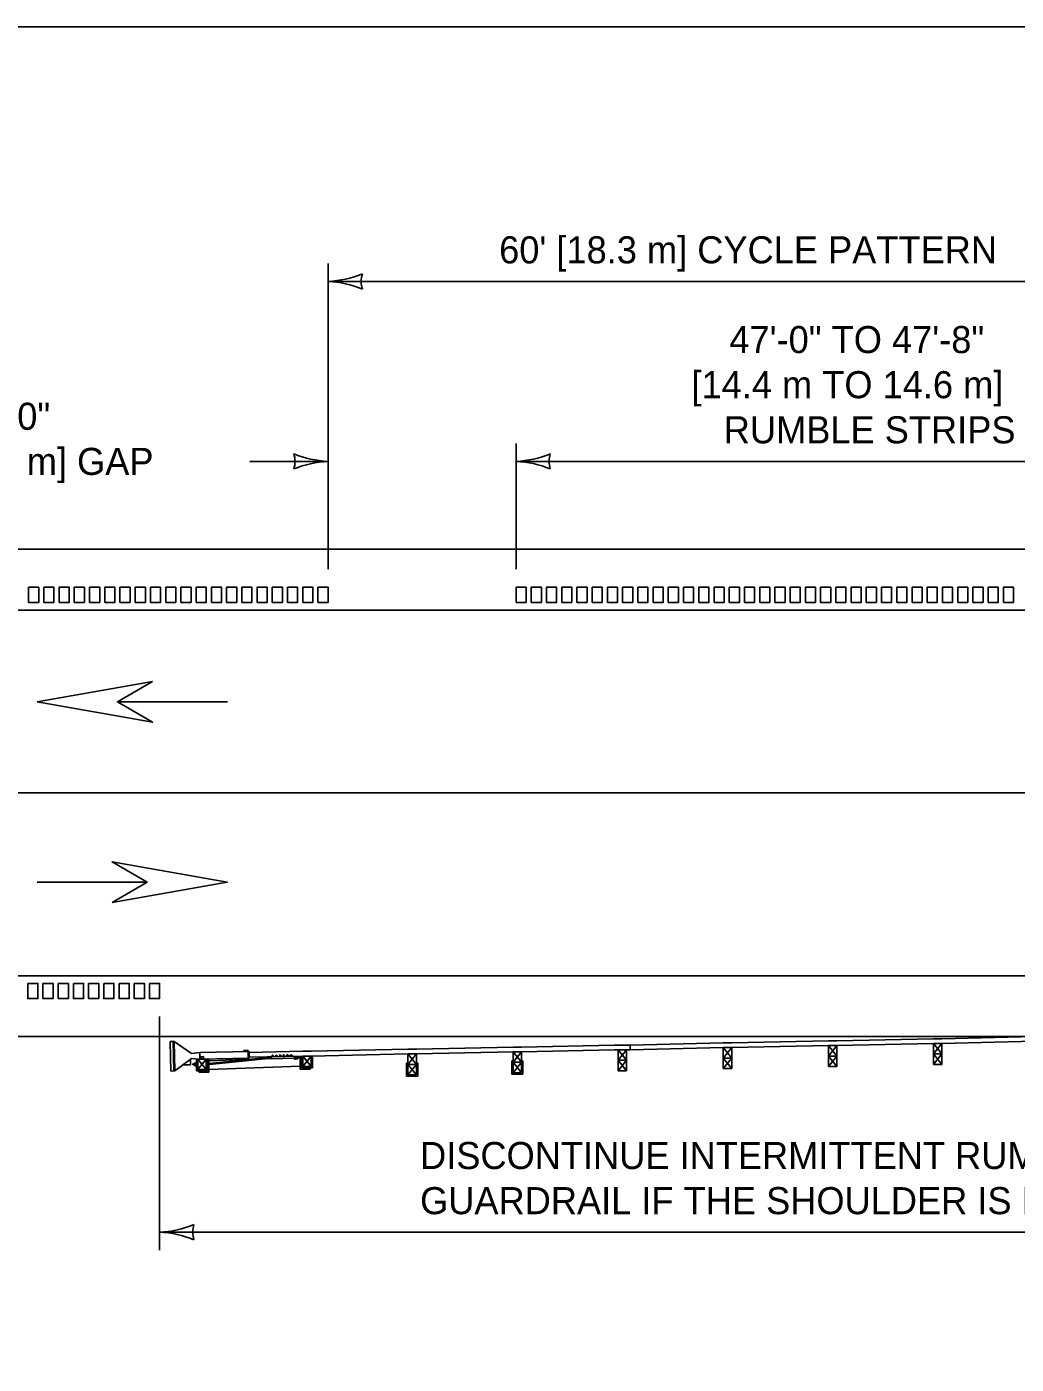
# Model space of a CAD drawing. Extents: x 49991.4 to 50021, y 49987.6 to 50011.4.
# Drawn here: x 50007.091 to 50009.283, y 49996.035 to 49998.999 of the extents above; entities that cross this region are included whole.
import ezdxf

# ---------------------------------------------------------------- set-up
doc = ezdxf.new("R2010")
doc.units = 0
for name, color, linetype in [('Level 1', 7, 'Continuous'), ('Level 2', 7, 'Continuous'), ('Level 3', 7, 'Continuous')]:
    doc.layers.add(name, color=color, linetype=linetype)

msp = doc.modelspace()

# ---------------------------------------------------------------- linework, layer by layer
at = {"layer": 'Level 1'}
for p, q in [((50011.3288, 49997.8413), (50005.1053, 49997.8413)), ((50011.3288, 49997.7063), (50005.1053, 49997.7063)), ((50007.5356, 49997.5032), (50007.2917, 49997.5032)), ((50007.5356, 49997.5029), (50007.2917, 49997.5029)), ((50011.3288, 49997.3013), (50005.1053, 49997.3013)), ((50007.1138, 49997.1035), (50007.3577, 49997.1035)), ((50007.1138, 49997.1033), (50007.3577, 49997.1033)), ((50011.3288, 49996.8963), (50005.1053, 49996.8963)), ((50007.3676, 49996.7613), (50005.1053, 49996.7613)), ((50009.4632, 49996.7613), (50007.3676, 49996.7613)), ((50009.0999, 49996.7567), (50008.8856, 49996.752)), ((50009.0999, 49996.7567), (50009.1185, 49996.7567)), ((50009.3237, 49996.7613), (50009.1185, 49996.7567)), ((50007.4084, 49996.7501), (50007.4177, 49996.7503)), ((50007.4097, 49996.6849), (50007.4084, 49996.7501)), ((50007.4168, 49996.6851), (50007.4155, 49996.7503)), ((50007.419, 49996.6851), (50007.4177, 49996.7503)), ((50007.4177, 49996.7503), (50007.4555, 49996.724)), ((50007.4555, 49996.724), (50007.4741, 49996.7263)), ((50007.5834, 49996.7285), (50007.4741, 49996.7263)), ((50007.4744, 49996.7114), (50007.4741, 49996.7263)), ((50007.5812, 49996.7307), (50007.5719, 49996.7305)), ((50007.5719, 49996.7283), (50007.5719, 49996.7305)), ((50007.5816, 49996.7114), (50007.5812, 49996.7307)), ((50007.7026, 49996.7287), (50007.5834, 49996.7263)), ((50007.5837, 49996.7136), (50007.5834, 49996.7285)), ((50007.7026, 49996.7287), (50007.7213, 49996.7287)), ((50007.9355, 49996.7334), (50007.7213, 49996.7287)), ((50007.7213, 49996.7183), (50007.9355, 49996.723)), ((50007.9355, 49996.7334), (50007.9541, 49996.7334)), ((50007.9355, 49996.723), (50007.9541, 49996.6997)), ((50007.9355, 49996.6997), (50007.9541, 49996.723)), ((50007.9355, 49996.723), (50007.9355, 49996.6764)), ((50007.9355, 49996.723), (50007.9541, 49996.723)), ((50008.1684, 49996.7381), (50007.9541, 49996.7334)), ((50007.9541, 49996.723), (50008.1684, 49996.7276)), ((50007.9541, 49996.6764), (50007.9541, 49996.723)), ((50008.1684, 49996.7381), (50008.187, 49996.7381)), ((50008.1684, 49996.7276), (50008.187, 49996.7043)), ((50008.1684, 49996.7043), (50008.187, 49996.7276)), ((50008.1684, 49996.7276), (50008.1684, 49996.681)), ((50008.1684, 49996.7276), (50008.187, 49996.7276)), ((50008.3922, 49996.7427), (50008.187, 49996.7381)), ((50008.187, 49996.7276), (50008.3922, 49996.7323)), ((50008.187, 49996.681), (50008.187, 49996.7276)), ((50008.3922, 49996.7427), (50008.4277, 49996.7427)), ((50008.3922, 49996.7323), (50008.4277, 49996.7323)), ((50008.4013, 49996.7323), (50008.4199, 49996.709)), ((50008.4013, 49996.709), (50008.4199, 49996.7323)), ((50008.4013, 49996.7323), (50008.4013, 49996.6857)), ((50008.4199, 49996.6857), (50008.4199, 49996.7323)), ((50008.6341, 49996.7474), (50008.4277, 49996.7427)), ((50008.4277, 49996.7323), (50008.4277, 49996.7427)), ((50008.4277, 49996.7323), (50008.6341, 49996.7369)), ((50008.6341, 49996.7474), (50008.6528, 49996.7474)), ((50008.6341, 49996.7369), (50008.6528, 49996.7136)), ((50008.6341, 49996.7136), (50008.6528, 49996.7369)), ((50008.6341, 49996.7369), (50008.6341, 49996.6904)), ((50008.6341, 49996.7369), (50008.6528, 49996.7369)), ((50008.867, 49996.752), (50008.6528, 49996.7474)), ((50008.6528, 49996.7369), (50008.867, 49996.7416)), ((50008.6528, 49996.6904), (50008.6528, 49996.7369)), ((50008.867, 49996.752), (50008.8856, 49996.752)), ((50008.867, 49996.7416), (50008.8856, 49996.7183)), ((50008.867, 49996.7183), (50008.8856, 49996.7416)), ((50008.867, 49996.7416), (50008.867, 49996.695)), ((50008.867, 49996.7416), (50008.8856, 49996.7416)), ((50008.8856, 49996.7416), (50009.0999, 49996.7463)), ((50008.8856, 49996.695), (50008.8856, 49996.7416)), ((50009.0999, 49996.7463), (50009.1185, 49996.723)), ((50009.0999, 49996.723), (50009.1185, 49996.7463)), ((50009.0999, 49996.7463), (50009.0999, 49996.6997)), ((50009.0999, 49996.7463), (50009.1185, 49996.7463)), ((50009.1185, 49996.6997), (50009.0999, 49996.723)), ((50009.0999, 49996.6997), (50009.1185, 49996.723)), ((50009.0999, 49996.723), (50009.1185, 49996.723)), ((50009.3237, 49996.7509), (50009.1185, 49996.7463)), ((50009.1185, 49996.6997), (50009.1185, 49996.7463)), ((50007.419, 49996.6851), (50007.4557, 49996.713)), ((50007.4538, 49996.699), (50007.4368, 49996.6986)), ((50007.4535, 49996.7113), (50007.4538, 49996.699)), ((50007.4557, 49996.713), (50007.4744, 49996.7114)), ((50007.4656, 49996.7008), (50007.4591, 49996.7008)), ((50007.4591, 49996.7008), (50007.4591, 49996.6989)), ((50007.4656, 49996.6989), (50007.4591, 49996.6989)), ((50007.4618, 49996.6972), (50007.4618, 49996.7026)), ((50007.4618, 49996.7026), (50007.4656, 49996.7026)), ((50007.4656, 49996.6972), (50007.4618, 49996.6972)), ((50007.4667, 49996.7042), (50007.4656, 49996.7042)), ((50007.4656, 49996.6953), (50007.4656, 49996.7042)), ((50007.4667, 49996.6953), (50007.4656, 49996.6953)), ((50007.4667, 49996.7121), (50007.4667, 49996.6851)), ((50007.4697, 49996.7114), (50007.4697, 49996.6851)), ((50007.4697, 49996.6881), (50007.4883, 49996.7114)), ((50007.4697, 49996.7114), (50007.4883, 49996.6881)), ((50007.4697, 49996.7114), (50007.4943, 49996.7114)), ((50007.5837, 49996.7136), (50007.4744, 49996.7114)), ((50007.4755, 49996.7167), (50007.4824, 49996.7169)), ((50007.4756, 49996.7114), (50007.4755, 49996.7167)), ((50007.4756, 49996.713), (50007.4825, 49996.7131)), ((50007.4825, 49996.7116), (50007.4824, 49996.7169)), ((50007.6327, 49996.7155), (50007.4883, 49996.7008)), ((50007.6328, 49996.7136), (50007.4883, 49996.6989)), ((50007.4883, 49996.6881), (50007.4883, 49996.7114)), ((50007.491, 49996.6992), (50007.4901, 49996.701)), ((50007.4913, 49996.7011), (50007.4913, 49996.7114)), ((50007.4913, 49996.6851), (50007.4913, 49996.6992)), ((50007.4943, 49996.7014), (50007.4943, 49996.7114)), ((50007.5889, 49996.711), (50007.4943, 49996.7076)), ((50007.4943, 49996.6822), (50007.4943, 49996.6995)), ((50007.6967, 49996.696), (50007.4943, 49996.6886)), ((50007.4964, 49996.6997), (50007.4954, 49996.7015)), ((50007.5018, 49996.7003), (50007.5008, 49996.7021)), ((50007.5071, 49996.7008), (50007.5062, 49996.7026)), ((50007.5125, 49996.7014), (50007.5115, 49996.7032)), ((50007.5179, 49996.7019), (50007.5169, 49996.7037)), ((50007.5232, 49996.7025), (50007.5223, 49996.7043)), ((50007.5286, 49996.703), (50007.5276, 49996.7048)), ((50007.534, 49996.7036), (50007.533, 49996.7054)), ((50007.5394, 49996.7041), (50007.5384, 49996.7059)), ((50007.5447, 49996.7046), (50007.5438, 49996.7065)), ((50007.5501, 49996.7052), (50007.5491, 49996.707)), ((50007.5555, 49996.7057), (50007.5545, 49996.7075)), ((50007.5609, 49996.7063), (50007.5599, 49996.7081)), ((50007.5662, 49996.7068), (50007.5653, 49996.7086)), ((50007.5716, 49996.7074), (50007.5706, 49996.7092)), ((50007.5722, 49996.7112), (50007.5722, 49996.7134)), ((50007.5816, 49996.7114), (50007.5722, 49996.7112)), ((50007.577, 49996.7079), (50007.576, 49996.7097)), ((50007.5823, 49996.7085), (50007.5814, 49996.7103)), ((50007.7026, 49996.7183), (50007.5837, 49996.7159)), ((50007.5877, 49996.709), (50007.5867, 49996.7108)), ((50007.5931, 49996.7096), (50007.5921, 49996.7114)), ((50007.5984, 49996.7101), (50007.5975, 49996.7119)), ((50007.6038, 49996.7107), (50007.6029, 49996.7125)), ((50007.6092, 49996.7112), (50007.6082, 49996.713)), ((50007.6146, 49996.7118), (50007.6136, 49996.7136)), ((50007.6199, 49996.7123), (50007.619, 49996.7141)), ((50007.6328, 49996.7127), (50007.6192, 49996.7122)), ((50007.6253, 49996.7128), (50007.6243, 49996.7146)), ((50007.6306, 49996.7134), (50007.6297, 49996.7152)), ((50007.6327, 49996.7169), (50007.6328, 49996.7122)), ((50007.6328, 49996.7122), (50007.684, 49996.7133)), ((50007.6345, 49996.7202), (50007.6358, 49996.7203)), ((50007.6345, 49996.7202), (50007.6345, 49996.7169)), ((50007.6392, 49996.717), (50007.6358, 49996.7203)), ((50007.6427, 49996.7204), (50007.6427, 49996.7171)), ((50007.6427, 49996.7204), (50007.644, 49996.7204)), ((50007.6474, 49996.7172), (50007.644, 49996.7204)), ((50007.6509, 49996.7206), (50007.6509, 49996.7173)), ((50007.6509, 49996.7206), (50007.6522, 49996.7206)), ((50007.6555, 49996.7174), (50007.6522, 49996.7206)), ((50007.6591, 49996.7207), (50007.6604, 49996.7208)), ((50007.6591, 49996.7207), (50007.6591, 49996.7174)), ((50007.6638, 49996.7175), (50007.6604, 49996.7208)), ((50007.6672, 49996.7209), (50007.6673, 49996.7176)), ((50007.6672, 49996.7209), (50007.6686, 49996.7209)), ((50007.672, 49996.7177), (50007.6686, 49996.7209)), ((50007.6755, 49996.7211), (50007.6755, 49996.7178)), ((50007.6755, 49996.7211), (50007.6768, 49996.7211)), ((50007.6802, 49996.7178), (50007.6768, 49996.7211)), ((50007.684, 49996.7133), (50007.6839, 49996.7179)), ((50007.684, 49996.7133), (50007.6841, 49996.7112)), ((50007.6841, 49996.7112), (50007.6863, 49996.7113)), ((50007.6863, 49996.7113), (50007.6861, 49996.718)), ((50007.6863, 49996.7117), (50007.6874, 49996.7117)), ((50007.6873, 49996.718), (50007.6874, 49996.7117)), ((50007.6873, 49996.7175), (50007.6911, 49996.7175)), ((50007.6873, 49996.7157), (50007.6938, 49996.7159)), ((50007.6874, 49996.7139), (50007.6939, 49996.714)), ((50007.6912, 49996.7121), (50007.6874, 49996.7121)), ((50007.6911, 49996.7175), (50007.6912, 49996.7121)), ((50007.6939, 49996.714), (50007.6938, 49996.7159)), ((50007.6967, 49996.715), (50007.6939, 49996.7149)), ((50007.6967, 49996.6891), (50007.6967, 49996.7182)), ((50007.6996, 49996.692), (50007.6996, 49996.7182)), ((50007.7026, 49996.695), (50007.7213, 49996.7183)), ((50007.7213, 49996.695), (50007.7026, 49996.7183)), ((50007.7026, 49996.7183), (50007.7026, 49996.695)), ((50007.7026, 49996.7183), (50007.7213, 49996.7183)), ((50007.7213, 49996.695), (50007.7026, 49996.695)), ((50007.7213, 49996.695), (50007.7213, 49996.7183)), ((50007.7242, 49996.7184), (50007.7242, 49996.692)), ((50007.9325, 49996.7027), (50007.9355, 49996.7027)), ((50007.9325, 49996.6734), (50007.9325, 49996.7027)), ((50007.9541, 49996.6764), (50007.9355, 49996.6997)), ((50007.9355, 49996.6764), (50007.9541, 49996.6997)), ((50007.9355, 49996.6997), (50007.9541, 49996.6997)), ((50007.9541, 49996.7027), (50007.9571, 49996.7027)), ((50007.9571, 49996.7027), (50007.9571, 49996.6734)), ((50008.1654, 49996.7073), (50008.1684, 49996.7073)), ((50008.1654, 49996.6781), (50008.1654, 49996.7073)), ((50008.187, 49996.681), (50008.1684, 49996.7043)), ((50008.1684, 49996.681), (50008.187, 49996.7043)), ((50008.1684, 49996.7043), (50008.187, 49996.7043)), ((50008.187, 49996.7073), (50008.19, 49996.7073)), ((50008.19, 49996.7073), (50008.19, 49996.6781)), ((50008.4199, 49996.6857), (50008.4013, 49996.709)), ((50008.4013, 49996.6857), (50008.4199, 49996.709)), ((50008.4013, 49996.709), (50008.4199, 49996.709)), ((50008.6528, 49996.6904), (50008.6341, 49996.7136)), ((50008.6341, 49996.6904), (50008.6528, 49996.7136)), ((50008.6341, 49996.7136), (50008.6528, 49996.7136)), ((50008.8856, 49996.695), (50008.867, 49996.7183)), ((50008.867, 49996.695), (50008.8856, 49996.7183)), ((50008.867, 49996.7183), (50008.8856, 49996.7183)), ((50008.8856, 49996.695), (50008.867, 49996.695)), ((50009.1185, 49996.6997), (50009.0999, 49996.6997)), ((50007.4097, 49996.6849), (50007.419, 49996.6851)), ((50007.4667, 49996.6851), (50007.4913, 49996.6851)), ((50007.4697, 49996.6881), (50007.4883, 49996.6881)), ((50007.4724, 49996.6822), (50007.4724, 49996.6851)), ((50007.4724, 49996.6822), (50007.4943, 49996.6822)), ((50007.7189, 49996.6891), (50007.6967, 49996.6891)), ((50007.7242, 49996.692), (50007.6996, 49996.692)), ((50007.7189, 49996.6891), (50007.7189, 49996.692)), ((50007.9571, 49996.6734), (50007.9325, 49996.6734)), ((50007.9541, 49996.6764), (50007.9355, 49996.6764)), ((50008.19, 49996.6781), (50008.1654, 49996.6781)), ((50008.187, 49996.681), (50008.1684, 49996.681)), ((50008.4199, 49996.6857), (50008.4013, 49996.6857)), ((50008.6528, 49996.6904), (50008.6341, 49996.6904))]:
    msp.add_line(p, q, dxfattribs=at)
for points in [[(49999.3835, 49998.9992), (50016.7501, 49998.9992), (50016.7501, 49987.7988), (49999.3835, 49987.7988)], [(50007.0949, 49997.7235), (50007.1173, 49997.7235), (50007.1173, 49997.7572), (50007.0949, 49997.7572)], [(50007.1286, 49997.7235), (50007.151, 49997.7235), (50007.151, 49997.7572), (50007.1286, 49997.7572)], [(50007.1623, 49997.7235), (50007.1847, 49997.7235), (50007.1847, 49997.7572), (50007.1623, 49997.7572)], [(50007.1961, 49997.7235), (50007.2185, 49997.7235), (50007.2185, 49997.7572), (50007.1961, 49997.7572)], [(50007.2299, 49997.7235), (50007.2523, 49997.7235), (50007.2523, 49997.7572), (50007.2299, 49997.7572)], [(50007.2636, 49997.7235), (50007.286, 49997.7235), (50007.286, 49997.7572), (50007.2636, 49997.7572)], [(50007.2973, 49997.7235), (50007.3197, 49997.7235), (50007.3197, 49997.7572), (50007.2973, 49997.7572)], [(50007.3311, 49997.7235), (50007.3535, 49997.7235), (50007.3535, 49997.7572), (50007.3311, 49997.7572)], [(50007.3649, 49997.7235), (50007.3873, 49997.7235), (50007.3873, 49997.7572), (50007.3649, 49997.7572)], [(50007.3986, 49997.7235), (50007.421, 49997.7235), (50007.421, 49997.7572), (50007.3986, 49997.7572)], [(50007.4323, 49997.7235), (50007.4547, 49997.7235), (50007.4547, 49997.7572), (50007.4323, 49997.7572)], [(50007.4661, 49997.7235), (50007.4885, 49997.7235), (50007.4885, 49997.7572), (50007.4661, 49997.7572)], [(50007.4999, 49997.7235), (50007.5223, 49997.7235), (50007.5223, 49997.7572), (50007.4999, 49997.7572)], [(50007.5336, 49997.7235), (50007.556, 49997.7235), (50007.556, 49997.7572), (50007.5336, 49997.7572)], [(50007.5673, 49997.7235), (50007.5897, 49997.7235), (50007.5897, 49997.7572), (50007.5673, 49997.7572)], [(50007.6011, 49997.7235), (50007.6235, 49997.7235), (50007.6235, 49997.7572), (50007.6011, 49997.7572)], [(50007.6349, 49997.7235), (50007.6573, 49997.7235), (50007.6573, 49997.7572), (50007.6349, 49997.7572)], [(50007.6686, 49997.7235), (50007.691, 49997.7235), (50007.691, 49997.7572), (50007.6686, 49997.7572)], [(50007.7023, 49997.7235), (50007.7247, 49997.7235), (50007.7247, 49997.7572), (50007.7023, 49997.7572)], [(50007.7361, 49997.7235), (50007.7585, 49997.7235), (50007.7585, 49997.7572), (50007.7361, 49997.7572)], [(50008.1749, 49997.7235), (50008.1973, 49997.7235), (50008.1973, 49997.7572), (50008.1749, 49997.7572)], [(50008.2087, 49997.7235), (50008.2311, 49997.7235), (50008.2311, 49997.7572), (50008.2087, 49997.7572)], [(50008.2424, 49997.7235), (50008.2648, 49997.7235), (50008.2648, 49997.7572), (50008.2424, 49997.7572)], [(50008.2761, 49997.7235), (50008.2985, 49997.7235), (50008.2985, 49997.7572), (50008.2761, 49997.7572)], [(50008.3099, 49997.7235), (50008.3323, 49997.7235), (50008.3323, 49997.7572), (50008.3099, 49997.7572)], [(50008.3437, 49997.7235), (50008.3661, 49997.7235), (50008.3661, 49997.7572), (50008.3437, 49997.7572)], [(50008.3774, 49997.7235), (50008.3998, 49997.7235), (50008.3998, 49997.7572), (50008.3774, 49997.7572)], [(50008.4111, 49997.7235), (50008.4335, 49997.7235), (50008.4335, 49997.7572), (50008.4111, 49997.7572)], [(50008.4449, 49997.7235), (50008.4673, 49997.7235), (50008.4673, 49997.7572), (50008.4449, 49997.7572)], [(50008.4787, 49997.7235), (50008.5011, 49997.7235), (50008.5011, 49997.7572), (50008.4787, 49997.7572)], [(50008.5124, 49997.7235), (50008.5348, 49997.7235), (50008.5348, 49997.7572), (50008.5124, 49997.7572)], [(50008.5461, 49997.7235), (50008.5685, 49997.7235), (50008.5685, 49997.7572), (50008.5461, 49997.7572)], [(50008.5799, 49997.7235), (50008.6023, 49997.7235), (50008.6023, 49997.7572), (50008.5799, 49997.7572)], [(50008.6137, 49997.7235), (50008.6361, 49997.7235), (50008.6361, 49997.7572), (50008.6137, 49997.7572)], [(50008.6474, 49997.7235), (50008.6698, 49997.7235), (50008.6698, 49997.7572), (50008.6474, 49997.7572)], [(50008.6811, 49997.7235), (50008.7035, 49997.7235), (50008.7035, 49997.7572), (50008.6811, 49997.7572)], [(50008.7149, 49997.7235), (50008.7373, 49997.7235), (50008.7373, 49997.7572), (50008.7149, 49997.7572)], [(50008.7487, 49997.7235), (50008.7711, 49997.7235), (50008.7711, 49997.7572), (50008.7487, 49997.7572)], [(50008.7824, 49997.7235), (50008.8048, 49997.7235), (50008.8048, 49997.7572), (50008.7824, 49997.7572)], [(50008.8161, 49997.7235), (50008.8385, 49997.7235), (50008.8385, 49997.7572), (50008.8161, 49997.7572)], [(50008.8499, 49997.7235), (50008.8723, 49997.7235), (50008.8723, 49997.7572), (50008.8499, 49997.7572)], [(50008.8837, 49997.7235), (50008.9061, 49997.7235), (50008.9061, 49997.7572), (50008.8837, 49997.7572)], [(50008.9174, 49997.7235), (50008.9398, 49997.7235), (50008.9398, 49997.7572), (50008.9174, 49997.7572)], [(50008.9511, 49997.7235), (50008.9735, 49997.7235), (50008.9735, 49997.7572), (50008.9511, 49997.7572)], [(50008.9849, 49997.7235), (50009.0073, 49997.7235), (50009.0073, 49997.7572), (50008.9849, 49997.7572)], [(50009.0187, 49997.7235), (50009.0411, 49997.7235), (50009.0411, 49997.7572), (50009.0187, 49997.7572)], [(50009.0524, 49997.7235), (50009.0748, 49997.7235), (50009.0748, 49997.7572), (50009.0524, 49997.7572)], [(50009.0861, 49997.7235), (50009.1085, 49997.7235), (50009.1085, 49997.7572), (50009.0861, 49997.7572)], [(50009.1199, 49997.7235), (50009.1423, 49997.7235), (50009.1423, 49997.7572), (50009.1199, 49997.7572)], [(50009.1537, 49997.7235), (50009.1761, 49997.7235), (50009.1761, 49997.7572), (50009.1537, 49997.7572)], [(50009.1874, 49997.7235), (50009.2098, 49997.7235), (50009.2098, 49997.7572), (50009.1874, 49997.7572)], [(50009.2211, 49997.7235), (50009.2435, 49997.7235), (50009.2435, 49997.7572), (50009.2211, 49997.7572)], [(50009.2549, 49997.7235), (50009.2773, 49997.7235), (50009.2773, 49997.7572), (50009.2549, 49997.7572)], [(50007.3697, 49997.5482), (50007.1141, 49997.5032), (50007.3697, 49997.4579), (50007.2917, 49997.5032)], [(50007.2797, 49997.0583), (50007.535, 49997.1033), (50007.2797, 49997.1486), (50007.3574, 49997.1033)], [(50007.093, 49996.8792), (50007.1155, 49996.8792), (50007.1155, 49996.8455), (50007.093, 49996.8455)], [(50007.1267, 49996.8792), (50007.1492, 49996.8792), (50007.1492, 49996.8455), (50007.1267, 49996.8455)], [(50007.1604, 49996.8792), (50007.1829, 49996.8792), (50007.1829, 49996.8455), (50007.1604, 49996.8455)], [(50007.1941, 49996.8792), (50007.2166, 49996.8792), (50007.2166, 49996.8455), (50007.1941, 49996.8455)], [(50007.2278, 49996.8792), (50007.2503, 49996.8792), (50007.2503, 49996.8455), (50007.2278, 49996.8455)], [(50007.2615, 49996.8792), (50007.284, 49996.8792), (50007.284, 49996.8455), (50007.2615, 49996.8455)], [(50007.2952, 49996.8792), (50007.3177, 49996.8792), (50007.3177, 49996.8455), (50007.2952, 49996.8455)], [(50007.3289, 49996.8792), (50007.3514, 49996.8792), (50007.3514, 49996.8455), (50007.3289, 49996.8455)], [(50007.3626, 49996.8792), (50007.3851, 49996.8792), (50007.3851, 49996.8455), (50007.3626, 49996.8455)]]:
    msp.add_lwpolyline(points, close=True, dxfattribs=at)
at = {"layer": 'Level 3'}
for p, q in [((50007.7585, 49998.4748), (50007.7585, 49997.7972)), ((50007.7585, 49998.4348), (50009.8173, 49998.4348)), ((50008.1749, 49998.076), (50008.1749, 49997.7972)), ((50007.5851, 49998.036), (50007.7585, 49998.036)), ((50008.1749, 49998.036), (50009.8173, 49998.036)), ((50007.3851, 49996.8055), (50007.3851, 49996.2878)), ((50007.3851, 49996.3278), (50011.2951, 49996.3278))]:
    msp.add_line(p, q, dxfattribs=at)
for centre, radius, start, end in [((50007.747, 49998.6675), 0.233, 272.8273, 292.0772), ((50007.8867, 49998.4348), 0.0548, 162.1388, 197.8612), ((50007.7493, 49998.2126), 0.2223, 67.456, 87.6395), ((50007.7677, 49998.2581), 0.2223, 247.456, 267.6395), ((50007.6303, 49998.036), 0.0548, 342.1388, 17.8612), ((50007.77, 49997.8033), 0.233, 92.8273, 112.0772), ((50008.1634, 49998.2687), 0.233, 272.8273, 292.0772), ((50008.1657, 49997.8139), 0.2223, 67.456, 87.6395), ((50008.3031, 49998.036), 0.0548, 162.1388, 197.8612), ((50007.3736, 49996.5605), 0.233, 272.8273, 292.0772), ((50007.5133, 49996.3278), 0.0548, 162.1388, 197.8612), ((50007.3759, 49996.1057), 0.2223, 67.456, 87.6395)]:
    msp.add_arc(centre, radius, start, end, dxfattribs=at)

# ---------------------------------------------------------------- texts
at = {"layer": 'Level 2'}
for s, p in [("60' [18.3 m] CYCLE PATTERN", (50008.1375, 49998.4748)), ('47\'-0" TO 47\'-8"', (50008.6477, 49998.276)), ('[14.4 m TO 14.6 m]', (50008.5636, 49998.176)), ('RUMBLE STRIPS', (50008.6353, 49998.076))]:
    msp.add_text(s, height=0.06, rotation=0.0001, dxfattribs=at).set_placement(p)
for s, p in [('12\'-4" TO 13\'-0"', (50006.578, 49998.106)), ('[3.7 m TO 3.9 m] GAP', (50006.578, 49998.006)), ('DISCONTINUE INTERMITTENT RUMBLE STRIPS IN FRONT OF ', (50007.9623, 49996.4678)), ("GUARDRAIL IF THE SHOULDER IS LESS THAN 6' [1.8 m] IN WIDTH.", (50007.9623, 49996.3678))]:
    msp.add_text(s, height=0.06, dxfattribs=at).set_placement(p)

doc.saveas('drawing.dxf')
